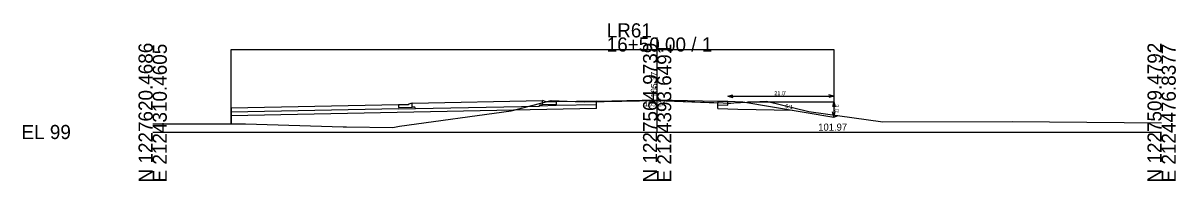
# Model space of a CAD drawing. Extents: x 2126751 to 2128979, y 1225108 to 1234639.
# Drawn here: x 2127750.9 to 2127979.4, y 1231607.5 to 1231638.8 of the extents above; entities that cross this region are included whole.
import ezdxf

# ---------------------------------------------------------------- set-up
doc = ezdxf.new("R2010")
doc.units = 0
for name, color, linetype in [('XS_CELL', 7, 'Continuous'), ('XS_M_DITCH', 7, 'Continuous'), ('XS_P_CURB_GUTTER', 7, 'Continuous'), ('XS_P_FINISHED_GRADE', 7, 'Continuous'), ('XS_P_FINISHED_GRADE_ELEV_TX', 7, 'Continuous'), ('XS_P_SUBGRADE_GRANULAR', 7, 'Continuous'), ('XS_P_SUBGRADE_GRANULAR_B', 7, 'Continuous'), ('XS_P_SUBGRADE_LEVELING', 7, 'Continuous'), ('XS_P_SUBGRADE_PAVEMENT', 7, 'Continuous'), ('XS_P_TX_CLEARZONE', 7, 'Continuous'), ('XS_P_TX_DCH', 7, 'Continuous'), ('XS_P_TX_FS_BS', 7, 'Continuous'), ('XS_X_GROUND', 7, 'Continuous'), ('XS_X_GROUND_TX', 7, 'Continuous')]:
    doc.layers.add(name, color=color, linetype=linetype)

msp = doc.modelspace()

# ---------------------------------------------------------------- linework, layer by layer
at = {"layer": 'XS_CELL'}
for p, q in [((2127876.61, 1231617.21), (2127876.61, 1231635.95)), ((2127776.61, 1231617.21), (2127876.61, 1231617.21)), ((2127876.61, 1231617.21), (2127976.61, 1231617.21))]:
    msp.add_line(p, q, dxfattribs=at)
at = {"layer": 'XS_M_DITCH'}
for p, q in [((2127792.16, 1231618.82), (2127792.16, 1231633.58)), ((2127792.16, 1231633.58), (2127911.61, 1231633.58)), ((2127911.61, 1231633.58), (2127911.61, 1231620.18))]:
    msp.add_line(p, q, dxfattribs=at)
at = {"layer": 'XS_P_CURB_GUTTER'}
for p, q in [((2127825.33, 1231622.58), (2127825.33, 1231622.08)), ((2127825.33, 1231622.08), (2127828.08, 1231622.13)), ((2127828.08, 1231622.13), (2127828.08, 1231622.94)), ((2127853.86, 1231622.62), (2127853.86, 1231623.45)), ((2127856.61, 1231622.68), (2127853.86, 1231622.62)), ((2127856.61, 1231623.18), (2127856.61, 1231622.68))]:
    msp.add_line(p, q, dxfattribs=at)
at = {"layer": 'XS_P_FINISHED_GRADE'}
for p, q in [((2127825.33, 1231622.58), (2127792.16, 1231621.92)), ((2127792.16, 1231621.92), (2127792.16, 1231618.82)), ((2127827.33, 1231622.62), (2127825.33, 1231622.58)), ((2127828.08, 1231622.94), (2127827.33, 1231622.7)), ((2127827.33, 1231622.7), (2127827.33, 1231622.62)), ((2127828.08, 1231622.94), (2127853.86, 1231623.45)), ((2127854.61, 1231623.22), (2127853.86, 1231623.45)), ((2127854.61, 1231623.14), (2127854.61, 1231623.22)), ((2127856.61, 1231623.18), (2127854.61, 1231623.14)), ((2127864.61, 1231623.34), (2127856.61, 1231623.18)), ((2127864.61, 1231623.34), (2127876.61, 1231623.58)), ((2127876.61, 1231623.58), (2127888.61, 1231623.34)), ((2127888.61, 1231623.34), (2127890.61, 1231623.3)), ((2127890.61, 1231623.3), (2127893.61, 1231623.18)), ((2127893.61, 1231623.18), (2127911.61, 1231620.18)), ((2127911.61, 1231620.18), (2127912.5, 1231620.47))]:
    msp.add_line(p, q, dxfattribs=at)
at = {"layer": 'XS_P_SUBGRADE_GRANULAR'}
for p, q in [((2127864.61, 1231621.84), (2127792.16, 1231620.39)), ((2127864.61, 1231621.84), (2127864.61, 1231622.59)), ((2127888.61, 1231621.84), (2127888.61, 1231622.59)), ((2127888.61, 1231621.84), (2127888.61, 1231622.59)), ((2127888.61, 1231621.84), (2127890.61, 1231621.8)), ((2127888.61, 1231621.84), (2127890.62, 1231621.8)), ((2127890.61, 1231621.8), (2127892.61, 1231621.76)), ((2127890.62, 1231621.8), (2127892.62, 1231621.76)), ((2127892.61, 1231621.76), (2127903.43, 1231621.54)), ((2127892.62, 1231621.76), (2127903.44, 1231621.54))]:
    msp.add_line(p, q, dxfattribs=at)
at = {"layer": 'XS_P_SUBGRADE_GRANULAR_B'}
for p, q in [((2127828.08, 1231622.12), (2127828.08, 1231622.94)), ((2127828.58, 1231622.13), (2127828.08, 1231622.12)), ((2127828.72, 1231621.9), (2127828.58, 1231622.13)), ((2127828.72, 1231621.9), (2127853.21, 1231622.36)), ((2127853.21, 1231622.36), (2127853.36, 1231622.61)), ((2127853.36, 1231622.61), (2127853.86, 1231622.62)), ((2127853.86, 1231622.62), (2127853.86, 1231623.45))]:
    msp.add_line(p, q, dxfattribs=at)
at = {"layer": 'XS_P_SUBGRADE_LEVELING'}
for p, q in [((2127864.61, 1231623.34), (2127864.61, 1231623.21)), ((2127864.61, 1231623.21), (2127866.09, 1231623.24)), ((2127866.09, 1231623.24), (2127876.64, 1231623.45)), ((2127876.64, 1231623.45), (2127888.61, 1231623)), ((2127888.61, 1231623.34), (2127888.61, 1231623))]:
    msp.add_line(p, q, dxfattribs=at)
at = {"layer": 'XS_P_SUBGRADE_PAVEMENT'}
for p, q in [((2127825.33, 1231621.83), (2127792.16, 1231621.17)), ((2127825.33, 1231621.83), (2127828.58, 1231621.89)), ((2127828.58, 1231621.89), (2127828.72, 1231621.9)), ((2127853.36, 1231622.36), (2127853.21, 1231622.36)), ((2127856.61, 1231622.43), (2127853.36, 1231622.36)), ((2127864.61, 1231622.59), (2127856.61, 1231622.43)), ((2127864.61, 1231622.59), (2127864.61, 1231623.21)), ((2127888.61, 1231622.59), (2127888.61, 1231623)), ((2127888.61, 1231622.59), (2127890.61, 1231622.55)), ((2127890.61, 1231622.55), (2127890.61, 1231623.3))]:
    msp.add_line(p, q, dxfattribs=at)
at = {"layer": 'XS_P_TX_CLEARZONE'}
for p, q in [((2127890.61, 1231624.3), (2127891.61, 1231624.55)), ((2127890.61, 1231624.3), (2127891.61, 1231624.05)), ((2127890.61, 1231624.3), (2127911.61, 1231624.3)), ((2127911.61, 1231624.3), (2127910.61, 1231624.55)), ((2127911.61, 1231624.3), (2127910.61, 1231624.05)), ((2127911.62, 1231624.3), (2127910.62, 1231624.55)), ((2127911.62, 1231624.3), (2127910.62, 1231624.05)), ((2127894.61, 1231623.18), (2127911.61, 1231623.18)), ((2127894.62, 1231623.18), (2127911.62, 1231623.18)), ((2127911.61, 1231623.18), (2127911.36, 1231622.18)), ((2127911.62, 1231623.18), (2127911.37, 1231622.18)), ((2127911.61, 1231623.18), (2127911.61, 1231620.18)), ((2127911.61, 1231623.18), (2127911.86, 1231622.18)), ((2127911.62, 1231623.18), (2127911.62, 1231620.18)), ((2127911.62, 1231623.18), (2127911.87, 1231622.18)), ((2127911.61, 1231620.18), (2127911.36, 1231621.18)), ((2127911.62, 1231620.18), (2127911.37, 1231621.18)), ((2127911.61, 1231620.18), (2127911.86, 1231621.18)), ((2127911.62, 1231620.18), (2127911.87, 1231621.18))]:
    msp.add_line(p, q, dxfattribs=at)
at = {"layer": 'XS_X_GROUND'}
for p, q in [((2127847.69, 1231621.38), (2127855.59, 1231623.46)), ((2127855.59, 1231623.46), (2127860.37, 1231623.25)), ((2127860.37, 1231623.25), (2127862.26, 1231623.16)), ((2127862.26, 1231623.16), (2127866.09, 1231623.24)), ((2127866.09, 1231623.24), (2127876.64, 1231623.45)), ((2127876.64, 1231623.45), (2127889.72, 1231622.96)), ((2127889.72, 1231622.96), (2127890.65, 1231622.93)), ((2127890.65, 1231622.93), (2127891.21, 1231622.95)), ((2127891.21, 1231622.95), (2127891.83, 1231622.97)), ((2127891.83, 1231622.97), (2127898.3, 1231623.34)), ((2127898.3, 1231623.34), (2127906.7, 1231621.27)), ((2127825.52, 1231618.4), (2127847.69, 1231621.38)), ((2127906.7, 1231621.27), (2127921.36, 1231619.24)), ((2127776.61, 1231618.86), (2127779.83, 1231618.85)), ((2127779.83, 1231618.85), (2127780.84, 1231618.8)), ((2127780.84, 1231618.8), (2127794.99, 1231618.82)), ((2127794.99, 1231618.82), (2127814.39, 1231618.24)), ((2127814.39, 1231618.24), (2127815.03, 1231618.23)), ((2127815.03, 1231618.23), (2127824.24, 1231618.12)), ((2127824.24, 1231618.12), (2127825.52, 1231618.4)), ((2127921.36, 1231619.24), (2127946.96, 1231619.27)), ((2127946.96, 1231619.27), (2127976.61, 1231619.01))]:
    msp.add_line(p, q, dxfattribs=at)

# ---------------------------------------------------------------- texts
at = {"layer": 'XS_CELL'}
for s, p in [('LR61', (2127866.61, 1231635.95)), ('16+50.00 / 1', (2127866.61, 1231633.15)), ('EL 99', (2127750.61, 1231615.81))]:
    msp.add_text(s, height=2.8, dxfattribs=at).set_placement(p)
for s, p in [('N 1227620.4686', (2127776.61, 1231607.21)), ('E 2124310.4605', (2127779.41, 1231607.21)), ('N 1227564.9739', (2127876.61, 1231607.21)), ('E 2124393.6491', (2127879.41, 1231607.21)), ('N 1227509.4792', (2127976.61, 1231607.21)), ('E 2124476.8377', (2127979.41, 1231607.21))]:
    msp.add_text(s, height=2.8, rotation=90, dxfattribs=at).set_placement(p)
at = {"layer": 'XS_P_FINISHED_GRADE_ELEV_TX'}
msp.add_text(' 105.37', height=1.25, rotation=90, dxfattribs=at).set_placement((2127876.61, 1231623.58))
at = {"layer": 'XS_P_TX_CLEARZONE'}
msp.add_text("21.0'", height=0.8, dxfattribs=at).set_placement((2127899.82, 1231624.5))
msp.add_text("3.0'", height=0.8, rotation=270, dxfattribs=at).set_placement((2127911.81, 1231622.7))
at = {"layer": 'XS_P_TX_DCH'}
msp.add_text('101.97', height=1.4, dxfattribs=at).set_placement((2127908.54, 1231617.48))
at = {"layer": 'XS_P_TX_FS_BS'}
msp.add_text('6:1', height=0.8, rotation=350.5377, dxfattribs=at).set_placement((2127901.95, 1231621.99))
at = {"layer": 'XS_X_GROUND_TX'}
msp.add_text('105.24', height=1, dxfattribs=at).set_placement((2127874.05, 1231622.29))

doc.saveas('drawing.dxf')
